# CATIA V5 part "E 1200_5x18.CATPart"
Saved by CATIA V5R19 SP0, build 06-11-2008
Nomenclature: E 1200_5x18
Description: PART-E 1200_5x18-DESC
Property "Hersteller": "Meusburger"
Property "Material": "12.9 ISO 4762 (DIN 912)"
Property "Bestellnummer": "E 1200/5x18"
Property "Teilenummer": "E 1200/5x18"
Property "Beschreibung": "Zylinderkopfschraube mit Innensechskant _ Cylinder head screw with hexagon socket"
Material "Steel": density 7860 kg/m3, Young's modulus 2e+11 Pa, Poisson ratio 0.266, thermal expansion 1.17e-05 1/K
Bounding box of the stored display mesh (mm): x -4.25 to 4.25, y -4.24 to 4.24, z -18 to 5
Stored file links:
  G:\UTB\Kombinované\Bakalářská práce\Catia\FORMA\E 1200_5x18.CATPart
  D:\Aplikace\CATIA\Nová složka\win_b64\startup\materials\Catalog.CATMaterial
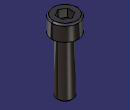
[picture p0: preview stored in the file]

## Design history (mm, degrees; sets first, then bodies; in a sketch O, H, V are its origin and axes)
Body1 "E 1200_5x18" (main body)
  Solid1: solid without history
